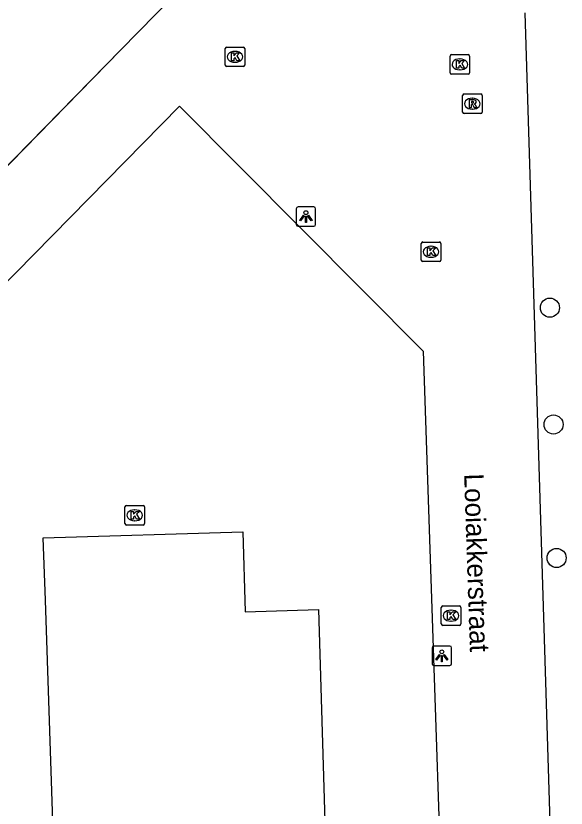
# Model space of a CAD drawing. Extents: x 161402 to 161933, y 381650 to 382313.
# Drawn here: x 161864.17 to 161892.38, y 382106.69 to 382147.3 of the extents above; entities that cross this region are included whole.
import ezdxf

# ---------------------------------------------------------------- set-up
doc = ezdxf.new("R2010")
doc.units = 0
for name, color, linetype in [('IMGEO_Boom', 7, 'Continuous'), ('IMGEO_Kolk', 7, 'Continuous'), ('IMGEO_Lichtpunt', 7, 'Continuous'), ('IMGEO_Muur', 7, 'Continuous'), ('IMGEO_Openbare_ruimte_label', 7, 'Continuous'), ('IMGEO_Pand', 7, 'Continuous'), ('IMGEO_Rijbaan_lokaal_open', 7, 'Continuous'), ('IMGEO_Rioolput', 7, 'Continuous')]:
    doc.layers.add(name, color=color, linetype=linetype)

msp = doc.modelspace()

# ---------------------------------------------------------------- linework, layer by layer
at = {"layer": 'IMGEO_Boom'}
for centre in [(161891.541, 382132.339), (161891.73, 382126.349), (161891.886, 382119.508)]:
    msp.add_circle(centre, 0.489, dxfattribs=at)
at = {"layer": 'IMGEO_Kolk'}
for p, q in [((161874.9, 382144.77), (161874.9, 382145.622)), ((161874.975, 382145.696), (161875.827, 382145.696)), ((161875.388, 382145.476), (161875.413, 382145.476)), ((161875.901, 382145.622), (161875.901, 382144.77)), ((161886.428, 382144.384), (161886.428, 382145.236)), ((161886.503, 382145.31), (161887.355, 382145.31)), ((161886.916, 382145.09), (161886.941, 382145.09)), ((161887.429, 382145.236), (161887.429, 382144.384)), ((161875.827, 382144.696), (161874.975, 382144.696)), ((161875.411, 382144.916), (161875.386, 382144.916)), ((161887.355, 382144.31), (161886.503, 382144.31)), ((161886.939, 382144.53), (161886.914, 382144.53)), ((161885.025, 382135.705), (161885.877, 382135.705)), ((161884.95, 382134.779), (161884.95, 382135.631)), ((161885.438, 382135.485), (161885.463, 382135.485)), ((161885.951, 382135.631), (161885.951, 382134.779)), ((161885.461, 382134.925), (161885.436, 382134.925)), ((161885.877, 382134.705), (161885.025, 382134.705)), ((161869.761, 382121.271), (161869.761, 382122.123)), ((161869.836, 382122.197), (161870.688, 382122.197)), ((161870.249, 382121.977), (161870.274, 382121.977)), ((161870.762, 382122.123), (161870.762, 382121.271)), ((161870.688, 382121.197), (161869.836, 382121.197)), ((161870.272, 382121.417), (161870.247, 382121.417)), ((161885.975, 382116.126), (161885.975, 382116.978)), ((161886.05, 382117.052), (161886.902, 382117.052)), ((161886.976, 382116.978), (161886.976, 382116.126)), ((161886.463, 382116.832), (161886.488, 382116.832)), ((161886.486, 382116.272), (161886.461, 382116.272)), ((161886.902, 382116.052), (161886.05, 382116.052))]:
    msp.add_line(p, q, dxfattribs=at)
for points in [[(161874.9, 382144.77), (161874.9, 382145.622)], [(161874.975, 382145.696), (161875.827, 382145.696)], [(161875.901, 382145.622), (161875.901, 382144.77)], [(161875.221, 382145.396), (161875.344, 382145.396), (161875.344, 382145.245), (161875.474, 382145.396), (161875.638, 382145.396), (161875.492, 382145.245), (161875.645, 382144.996), (161875.493, 382144.996), (161875.408, 382145.16), (161875.344, 382145.093), (161875.344, 382144.996), (161875.221, 382144.996), (161875.221, 382145.396)], [(161886.428, 382144.384), (161886.428, 382145.236)], [(161886.503, 382145.31), (161887.355, 382145.31)], [(161886.749, 382145.01), (161886.872, 382145.01), (161886.872, 382144.859), (161887.002, 382145.01), (161887.166, 382145.01), (161887.02, 382144.859), (161887.173, 382144.61), (161887.021, 382144.61), (161886.936, 382144.774), (161886.872, 382144.707), (161886.872, 382144.61), (161886.749, 382144.61), (161886.749, 382145.01)], [(161887.429, 382145.236), (161887.429, 382144.384)], [(161875.827, 382144.696), (161874.975, 382144.696)], [(161887.355, 382144.31), (161886.503, 382144.31)], [(161885.025, 382135.705), (161885.877, 382135.705)], [(161884.95, 382134.779), (161884.95, 382135.631)], [(161885.271, 382135.405), (161885.394, 382135.405), (161885.394, 382135.254), (161885.524, 382135.405), (161885.688, 382135.405), (161885.542, 382135.254), (161885.695, 382135.005), (161885.543, 382135.005), (161885.458, 382135.169), (161885.394, 382135.102), (161885.394, 382135.005), (161885.271, 382135.005), (161885.271, 382135.405)], [(161885.951, 382135.631), (161885.951, 382134.779)], [(161885.877, 382134.705), (161885.025, 382134.705)], [(161869.761, 382121.271), (161869.761, 382122.123)], [(161869.836, 382122.197), (161870.688, 382122.197)], [(161870.082, 382121.897), (161870.205, 382121.897), (161870.205, 382121.746), (161870.335, 382121.897), (161870.499, 382121.897), (161870.353, 382121.746), (161870.506, 382121.497), (161870.354, 382121.497), (161870.269, 382121.661), (161870.205, 382121.594), (161870.205, 382121.497), (161870.082, 382121.497), (161870.082, 382121.897)], [(161870.762, 382122.123), (161870.762, 382121.271)], [(161870.688, 382121.197), (161869.836, 382121.197)], [(161885.975, 382116.126), (161885.975, 382116.978)], [(161886.05, 382117.052), (161886.902, 382117.052)], [(161886.976, 382116.978), (161886.976, 382116.126)], [(161886.296, 382116.752), (161886.419, 382116.752), (161886.419, 382116.601), (161886.549, 382116.752), (161886.713, 382116.752), (161886.567, 382116.601), (161886.72, 382116.352), (161886.568, 382116.352), (161886.483, 382116.516), (161886.419, 382116.449), (161886.419, 382116.352), (161886.296, 382116.352), (161886.296, 382116.752)], [(161886.902, 382116.052), (161886.05, 382116.052)]]:
    msp.add_lwpolyline(points, dxfattribs=at)
for centre, start, end in [((161874.977, 382145.62), 91.552, 178.448), ((161874.977, 382145.62), 91.552, 178.448), ((161875.825, 382145.62), 1.552, 88.448), ((161875.825, 382145.62), 1.552, 88.448), ((161886.505, 382145.234), 91.552, 178.448), ((161886.505, 382145.234), 91.552, 178.448), ((161887.353, 382145.234), 1.552, 88.448), ((161887.353, 382145.234), 1.552, 88.448), ((161874.977, 382144.772), 181.552, 268.448), ((161874.977, 382144.772), 181.552, 268.448), ((161875.825, 382144.772), 271.552, 358.448), ((161875.825, 382144.772), 271.552, 358.448), ((161886.505, 382144.386), 181.552, 268.448), ((161886.505, 382144.386), 181.552, 268.448), ((161887.353, 382144.386), 271.552, 358.448), ((161887.353, 382144.386), 271.552, 358.448), ((161885.027, 382135.629), 91.552, 178.448), ((161885.027, 382135.629), 91.552, 178.448), ((161885.875, 382135.629), 1.552, 88.448), ((161885.875, 382135.629), 1.552, 88.448), ((161885.027, 382134.781), 181.552, 268.448), ((161885.027, 382134.781), 181.552, 268.448), ((161885.875, 382134.781), 271.552, 358.448), ((161885.875, 382134.781), 271.552, 358.448), ((161869.838, 382122.121), 91.552, 178.448), ((161869.838, 382122.121), 91.552, 178.448), ((161870.686, 382122.121), 1.552, 88.448), ((161870.686, 382122.121), 1.552, 88.448), ((161869.838, 382121.273), 181.552, 268.448), ((161869.838, 382121.273), 181.552, 268.448), ((161870.686, 382121.273), 271.552, 358.448), ((161870.686, 382121.273), 271.552, 358.448), ((161886.052, 382116.976), 91.552, 178.448), ((161886.052, 382116.976), 91.552, 178.448), ((161886.9, 382116.976), 1.552, 88.448), ((161886.9, 382116.976), 1.552, 88.448), ((161886.052, 382116.128), 181.552, 268.448), ((161886.052, 382116.128), 181.552, 268.448), ((161886.9, 382116.128), 271.552, 358.448), ((161886.9, 382116.128), 271.552, 358.448)]:
    msp.add_arc(centre, 0.0765, start, end, dxfattribs=at)
for centre, major_axis, ratio, start_param, end_param in [((161875.387, 382145.196), (-0.387, 0.002), 0.722429, 4.712389, 7.853982), ((161875.412, 382145.196), (-0.39, 0.002), 0.717154, 1.570796, 4.712389), ((161886.915, 382144.81), (-0.387, 0.002), 0.722429, 4.712389, 7.853982), ((161886.94, 382144.81), (-0.39, 0.002), 0.717154, 1.570796, 4.712389), ((161885.437, 382135.205), (-0.387, 0.002), 0.722429, 4.712389, 7.853982), ((161885.462, 382135.205), (-0.39, 0.002), 0.717154, 1.570796, 4.712389), ((161870.248, 382121.697), (-0.387, 0.002), 0.722429, 4.712389, 7.853982), ((161870.273, 382121.697), (-0.39, 0.002), 0.717154, 1.570796, 4.712389), ((161886.462, 382116.552), (-0.387, 0.002), 0.722429, 4.712389, 7.853982), ((161886.487, 382116.552), (-0.39, 0.002), 0.717154, 1.570796, 4.712389)]:
    msp.add_ellipse(centre, major_axis=major_axis, ratio=ratio, start_param=start_param, end_param=end_param, dxfattribs=at)
at = {"layer": 'IMGEO_Lichtpunt'}
for p, q in [((161878.538, 382137.412), (161878.538, 382136.605)), ((161878.538, 382137.412), (161878.538, 382136.605)), ((161879.44, 382137.507), (161878.632, 382137.507)), ((161879.44, 382137.507), (161878.632, 382137.507)), ((161879.534, 382136.605), (161879.534, 382137.412)), ((161879.534, 382136.605), (161879.534, 382137.412)), ((161878.632, 382136.511), (161879.44, 382136.511)), ((161878.632, 382136.511), (161879.44, 382136.511)), ((161886.406, 382114.993), (161885.598, 382114.993)), ((161886.406, 382114.993), (161885.598, 382114.993)), ((161885.504, 382114.898), (161885.504, 382114.091)), ((161885.504, 382114.898), (161885.504, 382114.091)), ((161886.5, 382114.091), (161886.5, 382114.898)), ((161886.5, 382114.091), (161886.5, 382114.898)), ((161885.598, 382113.997), (161886.406, 382113.997)), ((161885.598, 382113.997), (161886.406, 382113.997))]:
    msp.add_line(p, q, dxfattribs=at)
for points in [[(161878.912, 382137.076), (161878.951, 382137.048), (161878.763, 382136.786), (161878.725, 382136.813), (161878.912, 382137.076)], [(161879.014, 382137.028), (161879.061, 382137.028), (161879.061, 382136.706), (161879.014, 382136.706), (161879.014, 382137.028)], [(161879.124, 382137.048), (161879.162, 382137.075), (161879.349, 382136.813), (161879.31, 382136.785), (161879.124, 382137.048)], [(161885.878, 382114.562), (161885.917, 382114.534), (161885.729, 382114.272), (161885.691, 382114.299), (161885.878, 382114.562)], [(161886.09, 382114.534), (161886.128, 382114.561), (161886.315, 382114.299), (161886.276, 382114.271), (161886.09, 382114.534)], [(161885.98, 382114.514), (161886.027, 382114.514), (161886.027, 382114.192), (161885.98, 382114.192), (161885.98, 382114.514)]]:
    msp.add_lwpolyline(points, dxfattribs=at)
for centre in [(161879.037, 382137.21), (161886.003, 382114.696)]:
    msp.add_circle(centre, 0.0994, dxfattribs=at)
for centre, start, end in [((161878.632, 382137.412), 90, 180), ((161878.632, 382137.412), 90, 180), ((161879.44, 382137.412), 0, 90), ((161879.44, 382137.412), 0, 90), ((161878.632, 382136.605), 180, 270), ((161878.632, 382136.605), 180, 270), ((161879.44, 382136.605), 270, 0), ((161879.44, 382136.605), 270, 360), ((161885.598, 382114.898), 90, 180), ((161885.598, 382114.898), 90, 180), ((161886.406, 382114.898), 0, 90), ((161886.406, 382114.898), 0, 90), ((161885.598, 382114.091), 180, 270), ((161885.598, 382114.091), 180, 270), ((161886.406, 382114.091), 270, 0), ((161886.406, 382114.091), 270, 360)]:
    msp.add_arc(centre, 0.0946, start, end, dxfattribs=at)
at = {"layer": 'IMGEO_Muur'}
for points in [[(161877.656, 382153.823), (161869.551, 382145.549)], [(161869.551, 382145.549), (161853.957, 382129.629)]]:
    msp.add_lwpolyline(points, dxfattribs=at)
at = {"layer": 'IMGEO_Pand'}
msp.add_lwpolyline([(161875.799, 382120.848), (161875.926, 382116.75), (161879.684, 382116.866), (161880.342, 382094.587), (161881.463, 382094.624), (161881.653, 382088.841), (161866.197, 382088.354), (161866.014, 382094.144), (161866.456, 382094.154), (161865.684, 382117.343), (161865.575, 382120.533), (161875.799, 382120.848)], dxfattribs=at)
at = {"layer": 'IMGEO_Rijbaan_lokaal_open'}
for points in [[(161877.656, 382153.823), (161869.551, 382145.549), (161859.667, 382135.458)], [(161891.937, 382093.79), (161890.273, 382147.456)], [(161863.229, 382133.182), (161872.557, 382142.66), (161885.051, 382130.105), (161886.502, 382086.978), (161881.604, 382083.709)]]:
    msp.add_lwpolyline(points, dxfattribs=at)
at = {"layer": 'IMGEO_Rioolput'}
for p, q in [((161887.068, 382142.368), (161887.068, 382143.22)), ((161887.143, 382143.294), (161887.995, 382143.294)), ((161887.556, 382143.074), (161887.581, 382143.074)), ((161888.069, 382143.22), (161888.069, 382142.368)), ((161887.995, 382142.294), (161887.143, 382142.294)), ((161887.579, 382142.514), (161887.554, 382142.514))]:
    msp.add_line(p, q, dxfattribs=at)
for points in [[(161887.068, 382142.368), (161887.068, 382143.22)], [(161887.143, 382143.294), (161887.995, 382143.294)], [(161887.657, 382142.992), (161887.405, 382142.994), (161887.405, 382142.594)], [(161888.069, 382143.22), (161888.069, 382142.368)], [(161887.405, 382142.594), (161887.529, 382142.594), (161887.529, 382142.756), (161887.54, 382142.756)], [(161887.583, 382142.913), (161887.529, 382142.913), (161887.529, 382142.832)], [(161887.529, 382142.832), (161887.581, 382142.832)], [(161887.587, 382142.727), (161887.658, 382142.594), (161887.798, 382142.594), (161887.733, 382142.72)], [(161887.995, 382142.294), (161887.143, 382142.294)]]:
    msp.add_lwpolyline(points, dxfattribs=at)
for centre, radius, start, end in [((161887.145, 382143.218), 0.0765, 91.552, 178.448), ((161887.145, 382143.218), 0.0765, 91.552, 178.448), ((161887.656, 382142.882), 0.109, 350.3612, 89.416), ((161887.993, 382143.218), 0.0765, 1.552, 88.448), ((161887.993, 382143.218), 0.0765, 1.552, 88.448), ((161887.539, 382142.703), 0.0533, 26.0293, 88.6989), ((161887.565, 382143.021), 0.19, 274.7715, 282.9687), ((161887.589, 382142.817), 0.0964, 77.0061, 93.1865), ((161887.603, 382142.874), 0.0378, 276.6634, 79.6772), ((161887.654, 382142.882), 0.112, 277.5842, 350.9817), ((161887.638, 382142.667), 0.108, 29.5134, 73.7905), ((161887.145, 382142.37), 0.0765, 181.552, 268.448), ((161887.145, 382142.37), 0.0765, 181.552, 268.448), ((161887.993, 382142.37), 0.0765, 271.552, 358.448), ((161887.993, 382142.37), 0.0765, 271.552, 358.448)]:
    msp.add_arc(centre, radius, start, end, dxfattribs=at)
for centre, major_axis, ratio, start_param, end_param in [((161887.555, 382142.794), (-0.387, 0.002), 0.722429, 4.712389, 7.853982), ((161887.58, 382142.794), (-0.39, 0.002), 0.717154, 1.570796, 4.712389)]:
    msp.add_ellipse(centre, major_axis=major_axis, ratio=ratio, start_param=start_param, end_param=end_param, dxfattribs=at)

# ---------------------------------------------------------------- texts
at = {"layer": 'IMGEO_Openbare_ruimte_label'}
msp.add_text('Looiakkerstraat', height=1, rotation=271.892, dxfattribs=at).set_placement((161887.146, 382123.821))

doc.saveas('drawing.dxf')
